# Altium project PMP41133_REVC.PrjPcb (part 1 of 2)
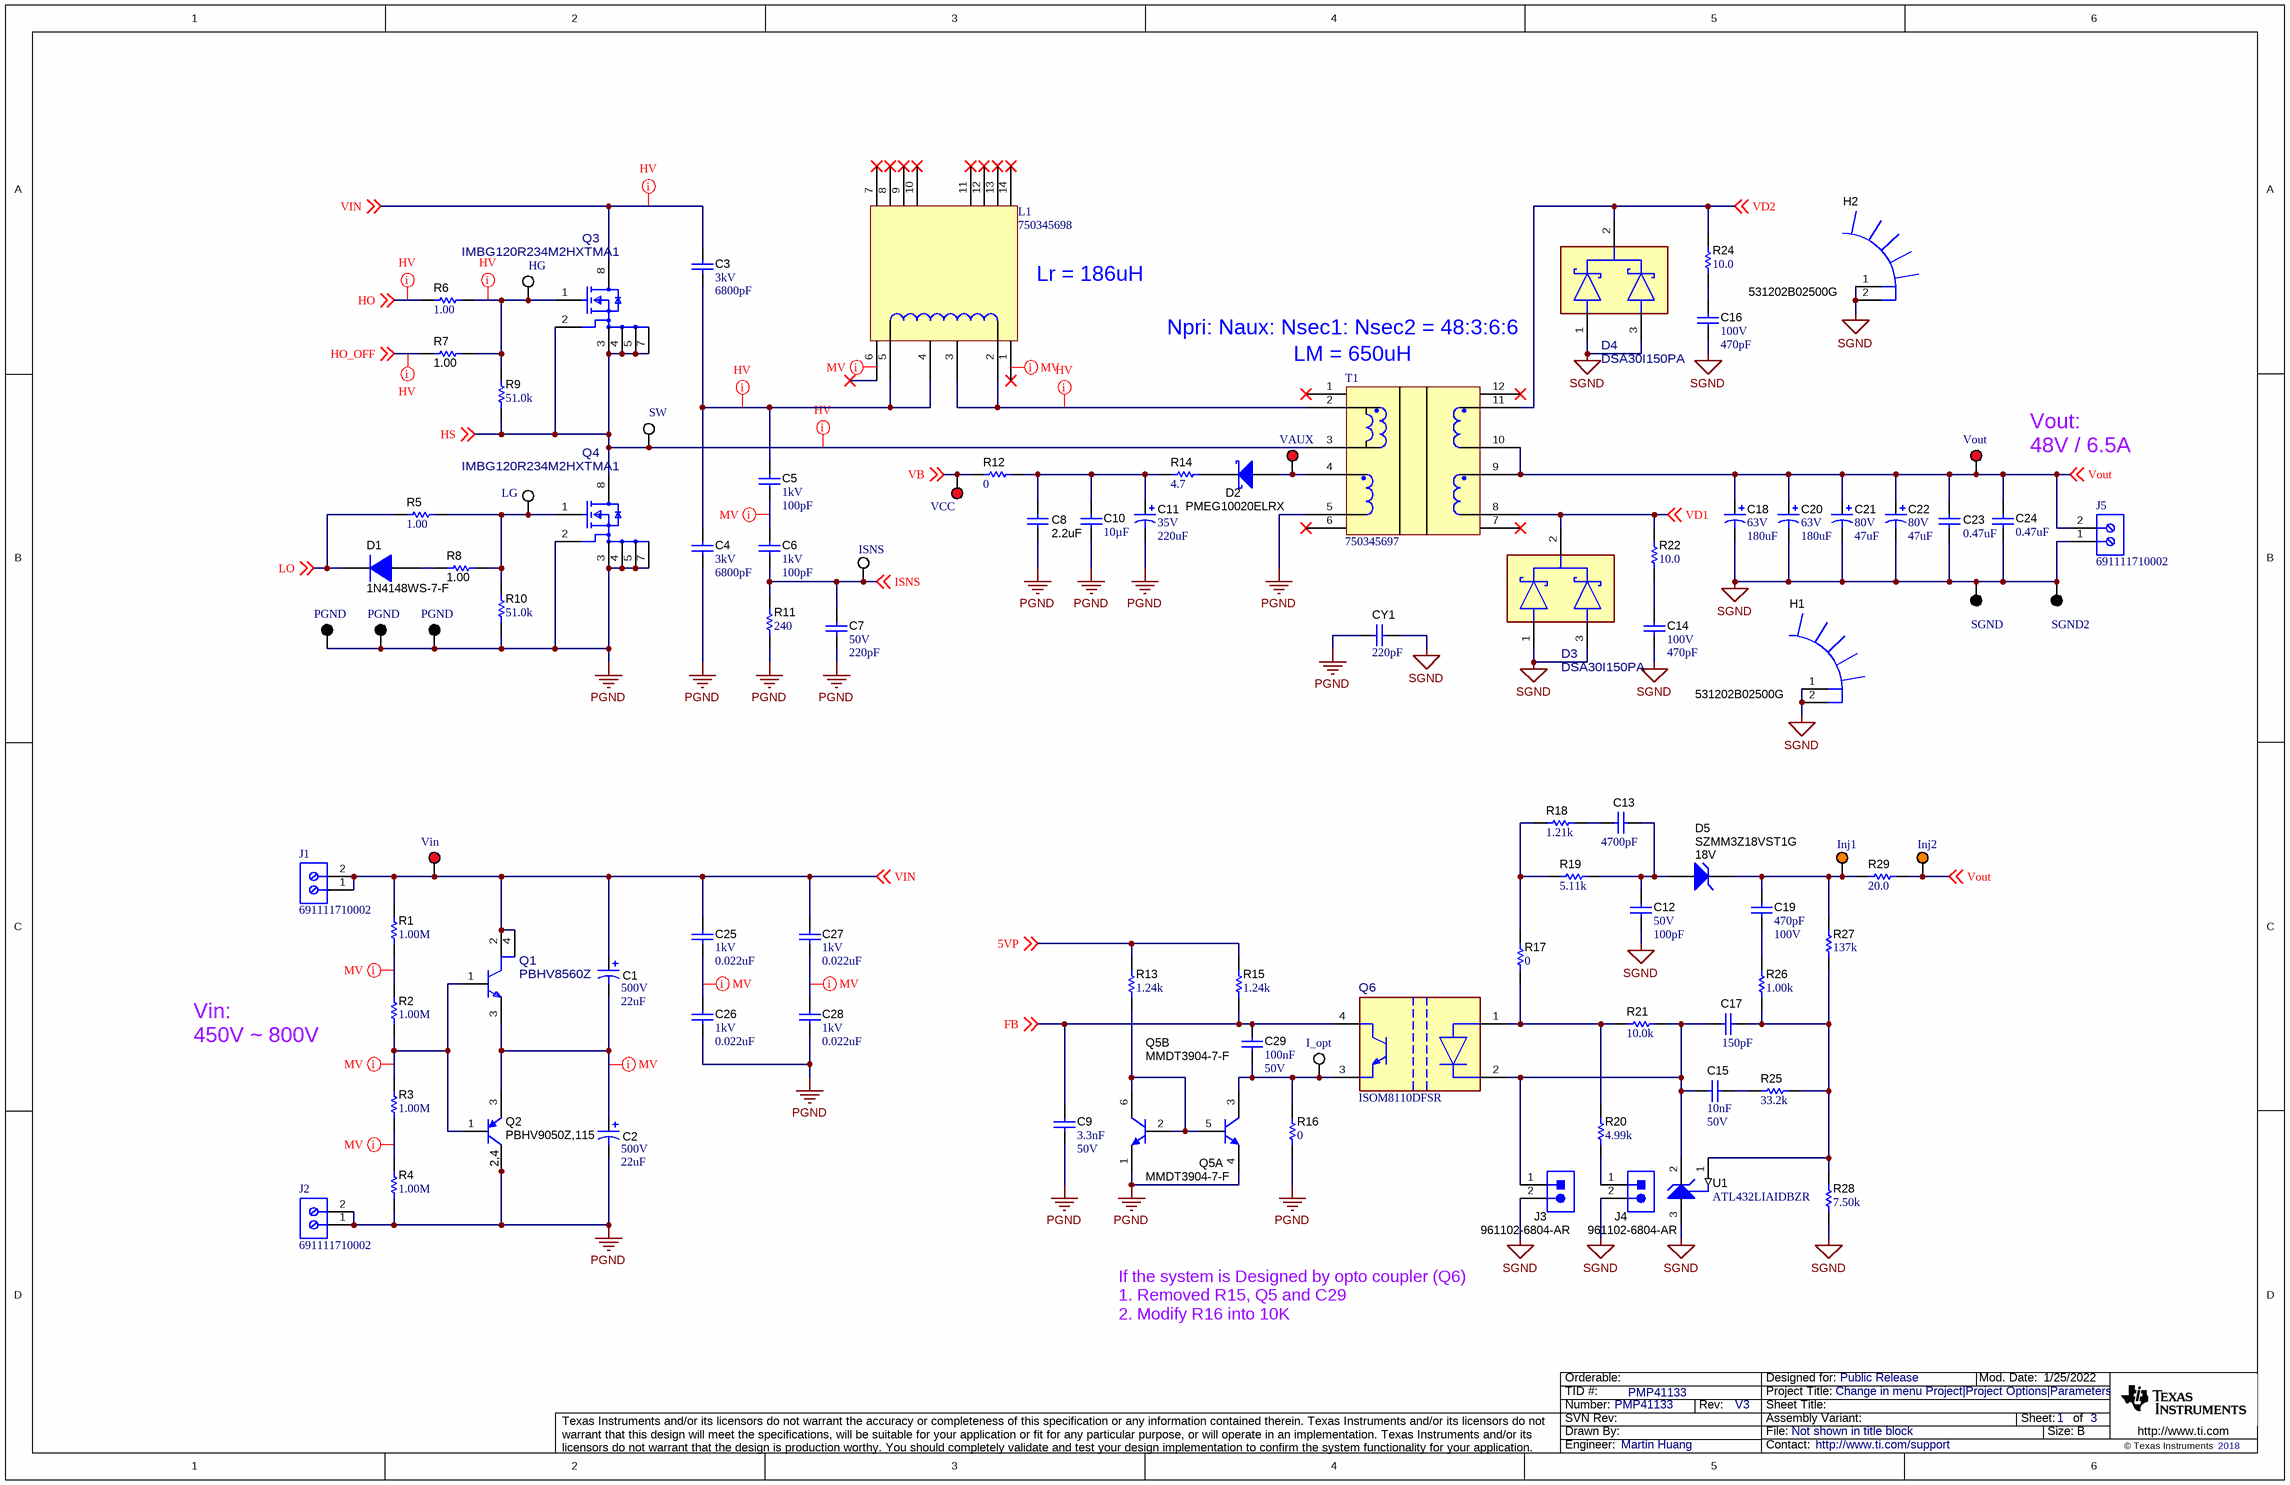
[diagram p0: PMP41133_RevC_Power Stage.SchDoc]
CopyrightYear: 2018; PCB_Layout: Martin Huang; PCB_Rev: E1; PRJ_Customer: Public Release; PRJ_Engineer: Martin Huang; PRJ_Number: PMP41133; PRJ_Title: Change in menu Project|Project Options|Parameters; SCH_Rev: V3; TechSupport: http://www.ti.com/support; TID: PMP41133
3 sheets, 184 parts. Net scope: global (net labels, ports and power ports of the same name join across sheets).
Board file: PMP41133_RevC.PcbDoc
Sheets:
  PMP41133_RevC_Power Stage.SchDoc
  PMP41133_RevC_Controller.SchDoc
  PMP41133_RevC_Hardware.SchDoc

## Sheet PMP41133_RevC_Power Stage.SchDoc
size 431 x 279 mm; Date: Not shown in title block; ApprovedBy: Not shown in title block; CheckedBy: Not shown in title block; Author: Not shown in title block; CompanyName: Not shown in title block; Engineer: Not shown in title block; Organization: Not shown in title block; Address1: Not shown in title block; Address2: Not shown in title block; Address3: Not shown in title block; Address4: Not shown in title block; DocumentNumber: 1; Revision: Use project parameter SCH_Rev; SheetNumber: 1; SheetTotal: 3; PageSetup: Record=PageOptions¦CenterHorizontal=True¦CenterVertical=True¦PrintScale=1.00¦XCorrection=1.00¦YCorrection=1.00¦PrintKind=0¦BorderSize=5000000¦LeftOffset=0¦BottomOffset=0¦Orientation=2¦PaperLength=1000¦PaperWidth=1000¦Scale=100¦PaperSource=15¦PrintQuality=600¦MediaType=1¦DitherType=10¦PaperKind=Letter¦PrintScaleMode=1

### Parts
(Parts that share a designator on the sheet are numbered #1, #2 ... from top to bottom, then left to right.)
C1  VDC_V: 500V  ValueDisplayed: 22uF  [UCY_1250x3550]  (hidden comment: UCY2H220MHD)
C2  VDC_V: 500V  ValueDisplayed: 22uF  [UCY_1250x3550]  (hidden comment: UCY2H220MHD)
C3  VDC_V: 3kV  ValueDisplayed: 6800pF  [B81123_2650x850x1650]  (hidden comment: B81123C1682M)
C4  VDC_V: 3kV  ValueDisplayed: 6800pF  [B81123_2650x850x1650]  (hidden comment: B81123C1682M)
C5  VDC_V: 1kV  ValueDisplayed: 100pF  [1206]  (hidden comment: VJ1206A101JXGAT5Z)
C6  VDC_V: 1kV  ValueDisplayed: 100pF  [1206]  (hidden comment: VJ1206A101JXGAT5Z)
C7  VDC_V: 50V  ValueDisplayed: 220pF  [0603]  (hidden comment: C0603C221K5GACTU)
C8  ValueDisplayed: 2.2uF  [0805]  (hidden comment: C2012X7R1V225K085AC)
C9  Cap_F: 3.3nF  VDC_V: 50V  [0603]  (hidden comment: GRM188R71H332KA01D)
C10  ValueDisplayed: 10µF  [1206]  (hidden comment: GRM31CR71E106MA12L)
C11  VDC_V: 35V  ValueDisplayed: 220uF  [M_800x1150]  (hidden comment: ECA-1VM221BJ)
C12  VDC_V: 50V  ValueDisplayed: 100pF  [0603]  (hidden comment: C0603C101J5GACTU)
C13  ValueDisplayed: 4700pF  [0603]  (hidden comment: GCM188R72A472KA37D)
C14  VDC_V: 100V  ValueDisplayed: 470pF  [0805]  (hidden comment: GRM2165C2A471JA01D)
C15  Cap_F: 10nF  VDC_V: 50V  [0603]  (hidden comment: GRM188R71H103KA01D)
C16  VDC_V: 100V  ValueDisplayed: 470pF  [0805]  (hidden comment: GRM2165C2A471JA01D)
C17  ValueDisplayed: 150pF  [0603]  (hidden comment: GRM1885C1H151JA01D)
C18  VDC_V: 63V  ValueDisplayed: 180uF  [UCZ_1250x1350]  (hidden comment: A783MW187M1JLASO15)
C19  Cap_F: 470pF  VDC_V: 100V  [0603]  (hidden comment: GRM188R72A471KA01D)
C20  VDC_V: 63V  ValueDisplayed: 180uF  [UCZ_1250x1350]  (hidden comment: A783MW187M1JLASO15)
C21  VDC_V: 80V  ValueDisplayed: 47uF  [PJ_800X1500]  (hidden comment: UPJ1K470MPD1TD)
C22  VDC_V: 80V  ValueDisplayed: 47uF  [PJ_800X1500]  (hidden comment: UPJ1K470MPD1TD)
C23  ValueDisplayed: 0.47uF  [0805]  (hidden comment: C2012X7S2A474K125AB)
C24  ValueDisplayed: 0.47uF  [0805]  (hidden comment: C2012X7S2A474K125AB)
C25  VDC_V: 1kV  ValueDisplayed: 0.022uF  [1206]  (hidden comment: VJ1206Y223KXGAT5Z)
C26  VDC_V: 1kV  ValueDisplayed: 0.022uF  [1206]  (hidden comment: VJ1206Y223KXGAT5Z)
C27  VDC_V: 1kV  ValueDisplayed: 0.022uF  [1206]  (hidden comment: VJ1206Y223KXGAT5Z)
C28  VDC_V: 1kV  ValueDisplayed: 0.022uF  [1206]  (hidden comment: VJ1206Y223KXGAT5Z)
C29  Cap_F: 100nF  VDC_V: 50V  [0603]  (hidden comment: C0603C104K5RACAUTO)
CY1  ValueDisplayed: 220pF  [DE1_800x700x1100]  (hidden comment: DE1B3KX221KA4BN01F)
D1  1N4148WS-7-F  [SOD-323]
D2  PMEG10020ELRX  [SOD-123W]
D3  DSA30I150PA  [FP-MBR30200CTE3_TU_TO220-3-MFG]
D4  DSA30I150PA  [FP-MBR30200CTE3_TU_TO220-3-MFG]
D5  SZMM3Z18VST1G  value 18V  [SOD-323]
H1  531202B02500G  [531202]
H2  531202B02500G  [531202]
HG  5012  [Keystone5012]  (value not drawn)
I_opt  5012  [Keystone5012]  (value not drawn)
Inj1  5013  [Keystone5013]  (value not drawn)
Inj2  5013  [Keystone5013]  (value not drawn)
ISNS  5012  [Keystone5012]  (value not drawn)
J1  691111710002  [691111710002]
J2  691111710002  [691111710002]
J3  961102-6804-AR  [3M_961102-68]
J4  961102-6804-AR  [3M_961102-68]
J5  691111710002  [691111710002]
L1  750345698  [Inductor 750345698]
LG  5012  [Keystone5012]  (value not drawn)
PGND#1  5011  [Keystone5011]  (value not drawn)
PGND#2  5011  [Keystone5011]  (value not drawn)
PGND#3  5011  [Keystone5011]  (value not drawn)
Q1  PBHV8560Z  [FP-PBHV8560Z_SOT-223-IPC_B]
Q2  PBHV9050Z,115  [SOT-223]
Q3  IMBG120R234M2HXTMA1  [FP-IMBG120R026M2HXTMA1_TO263-7-MFG]
Q4  IMBG120R234M2HXTMA1  [FP-IMBG120R026M2HXTMA1_TO263-7-MFG]
Q5  MMDT3904-7-F  [SOT-363]  (parts A,B of 2)
Q6  ISOM8110DFSR  [DFS0004A-MFG]
R1  ValueDisplayed: 1.00M  [1206]  (hidden comment: RC1206FR-071ML)
R2  ValueDisplayed: 1.00M  [1206]  (hidden comment: RC1206FR-071ML)
R3  ValueDisplayed: 1.00M  [1206]  (hidden comment: RC1206FR-071ML)
R4  ValueDisplayed: 1.00M  [1206]  (hidden comment: RC1206FR-071ML)
R5  ValueDisplayed: 1.00  [0603]  (hidden comment: RC0603FR-0742R2L)
R6  ValueDisplayed: 1.00  [0603]  (hidden comment: RC0603FR-0742R2L)
R7  ValueDisplayed: 1.00  [0603]  (hidden comment: RC0603FR-071RL)
R8  ValueDisplayed: 1.00  [0603]  (hidden comment: RC0603FR-071RL)
R9  ValueDisplayed: 51.0k  [0603]  (hidden comment: RC0603FR-0751KL)
R10  ValueDisplayed: 51.0k  [0603]  (hidden comment: RC0603FR-0751KL)
R11  ValueDisplayed: 240  [0603]  (hidden comment: RC0603FR-07240RL)
R12  ValueDisplayed: 0  [1206]  (hidden comment: CRCW12060000Z0EA)
R13  ValueDisplayed: 1.24k  [0603]  (hidden comment: RC0603FR-071K24L)
R14  ValueDisplayed: 4.7  [1206]  (hidden comment: CRCW12064R70JNEA)
R15  ValueDisplayed: 1.24k  [0603]  (hidden comment: RC0603FR-071K24L)
R16  ValueDisplayed: 0  [0603]  (hidden comment: MCR03EZPJ000)
R17  ValueDisplayed: 0  [0603]  (hidden comment: CRCW06030000Z0EA)
R18  ValueDisplayed: 1.21k  [0603]  (hidden comment: CRCW06031K21FKEA)
R19  ValueDisplayed: 5.11k  [0603]  (hidden comment: RC0603FR-075K11L)
R20  ValueDisplayed: 4.99k  [0603]  (hidden comment: CRCW06034K99FKEA)
R21  ValueDisplayed: 10.0k  [0603]  (hidden comment: RCG060310K0FKEA)
R22  ValueDisplayed: 10.0  [1206]  (hidden comment: RC1206FR-0710RL)
R24  ValueDisplayed: 10.0  [1206]  (hidden comment: RC1206FR-0710RL)
R25  ValueDisplayed: 33.2k  [0603]  (hidden comment: CRCW060333K2FKEA)
R26  ValueDisplayed: 1.00k  [0603]  (hidden comment: RC0603FR-071KL)
R27  ValueDisplayed: 137k  [0603]  (hidden comment: RC0603FR-07137KL)
R28  ValueDisplayed: 7.50k  [0603]  (hidden comment: RC0603FR-077K5L)
R29  ValueDisplayed: 20.0  [0603]  (hidden comment: CRCW06030000Z0EA)
SGND  5011  [Keystone5011]  (value not drawn)
SGND2  5011  [Keystone5011]  (value not drawn)
SW  5012  [Keystone5012]  (value not drawn)
T1  750345697  [Transformer 750345697]
U1  ATL432LIAIDBZR  [DBZ0003A_N]
VAUX  5010  [Keystone5010]  (value not drawn)
VCC  5010  [Keystone5010]  (value not drawn)
Vin  5010  [Keystone5010]  (value not drawn)
Vout  5010  [Keystone5010]  (value not drawn)

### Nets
PGND: C2.2(-) C4.2 C7.2 C8.2 C9.2 C10.2 C11.2(-) C26.2 C28.2 CY1.2 J2.1 J2.2 PGND#1.1 PGND#2.1 PGND#3.1 Q2.2(C) Q2.4(C) Q4.2(Sense) Q4.3(Source) Q4.4(Source) Q4.5(Source) Q4.7(Source) Q5.1(E) Q5.4(E) R4.1 R10.1 R11.1 R16.1 T1.5
SGND: C12.2 C14.2 C16.2 C18.2(-) C20.2(-) C21.2(-) C22.2(-) C23.1 C24.1 CY1.1 D3.1(1_ANODE) D3.3(2_ANODE) D4.1(1_ANODE) D4.3(2_ANODE) H1.1 H1.2 H2.1 H2.2 J3.2 J4.2 J5.1 R28.1 SGND.1 SGND2.1 U1.3(ANODE)
5VP: R13.2 R15.2 ; off-sheet 5VP
FB: C9.1 C29.1 Q6.4(COL) R15.1 ; off-sheet FB
HO: R6.1 ; off-sheet HO
HO_OFF: R7.1 ; off-sheet HO_OFF
HS: Q3.2(Sense) Q3.3(Source) Q3.4(Source) Q3.5(Source) Q3.7(Source) Q4.8(Drain) R9.1 SW.1 T1.3 ; off-sheet HS
ISNS: C6.2 C7.1 ISNS.1 R11.2 ; off-sheet ISNS
LO: D1.1(K) R5.1 ; off-sheet LO
VB: R12.1 VCC.1 ; off-sheet VB
VD1: D3.2(COMMON_CATHODE) R22.2 T1.8 ; off-sheet VD1
VD2: D4.2(COMMON_CATHODE) R24.2 T1.11 ; off-sheet VD2
VIN: C1.1(+) C3.1 C25.1 C27.1 J1.1 J1.2 Q1.2(C) Q1.4(C) Q3.8(Drain) R1.2 Vin.1 ; off-sheet VIN
Vout: C18.1(+) C20.1(+) C21.1(+) C22.1(+) C23.2 C24.2 Inj2.1 J5.2 R29.2 T1.9 T1.10 Vout.1 ; off-sheet Vout
NetC1_2: C1.2(-) C2.1(+) Q1.3(E) Q2.3(E)
NetC3_2: C3.2 C4.1 C5.1 L1.4 L1.5
NetC5_2: C5.2 C6.1
NetC8_1: C8.1 C10.1 C11.1(+) R12.2 R14.1
NetC12_1: C12.1 C13.1 D5.2(A) R19.2
NetC13_2: C13.2 R18.2
NetC14_1: C14.1 R22.1
NetC15_1: C15.1 C17.2 J3.1 Q6.2(CAT) R21.1 U1.2(CATHODE)
NetC15_2: C15.2 R25.2
NetC16_1: C16.1 R24.1
NetC17_1: C17.1 R25.1 R26.1 R27.1 R28.2 U1.1(REF)
NetC19_1: C19.1 D5.1(K) Inj1.1 R27.2 R29.1
NetC19_2: C19.2 R26.2
NetC25_2: C25.2 C26.1
NetC27_2: C27.2 C28.1
NetC29_2: C29.2 I_opt.1 Q5.3(C) Q6.3(EM) R16.2
NetD1_2: D1.2(A) R8.1
NetD2_1: D2.1(K) R14.2
NetD2_2: D2.2(A) T1.4 VAUX.1
NetHG_1: HG.1 Q3.1(Gate) R6.2 R7.2 R9.2
NetJ4_1: J4.1 R20.2
NetL1_2: L1.2 L1.3 T1.2
NetLG_1: LG.1 Q4.1(Gate) R5.2 R8.2 R10.2
NetQ1_1: Q1.1(B) Q2.1(B) R2.1 R3.2
NetQ5_2: Q5.2(B) Q5.5(B) Q5.6(C) R13.1
NetQ6_1: Q6.1(AN) R17.1 R20.1 R21.2
NetR1_1: R1.1 R2.2
NetR3_1: R3.1 R4.2
NetR17_2: R17.2 R18.1 R19.1

Not connected (* = marked no-connect by the designer): L1 1* 6* 7* 8* 9* 10* 11* 12* 13* 14*; T1 1* 6* 7* 12*

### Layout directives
net class HV: HO, HO_OFF, HS, NetC3_2, NetHG_1, NetL1_2, VIN
net class MV: (no net found under the mark), NetC1_2, NetC5_2, NetC25_2, NetC27_2, NetQ1_1, NetR1_1, NetR3_1

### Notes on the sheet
- (near L1) Lr = 186uH
- (near T1) LM = 650uH
- Npri: Naux: Nsec1: Nsec2 = 48:3:6:6
- Vout:
  48V / 6.5A
- Vin:
  450V ~ 800V
- If the system is Designed by opto coupler (Q6)
  1. Removed R15, Q5 and C29
  2. Modify R16 into 10K

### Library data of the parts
C1 C2 = CMP-0010255-2: CAP, AL, 22 uF, 500 V, +/- 20%, TH; Manufacturer: Nichicon; TaMin_C: -25°C; Polarized: Y; SizeAreaWB_mm2: 210.25; Value1: Unknown; Value: 22uF; TaMax_C: 105°C; SizeZ_mm: 37; SizeX_mm: 12.5; Cap_Case: 12.5x35.5mm; SizeArea_mm2: 156.25; CompType: Capacitor; AEC Qualified: N; Cap_F: 22µF; AEC Category: Q200; IRMS_A: 280mA; U/M: EA
C3 C4 = CMP-0012464-3: CAP, Film, 6800 pF, 3000 V, +/- 20%, TH; Manufacturer: TDK; TaMin_C: -40°C; Polarized: N; Value1: Unknown; Value: 6800pF; TaMax_C: 110°C; Cap_Case: 26.5x8.5x16.5mm; Value2: 3000V; Cap_F: 6.8nF; AEC Category: Q200
C5 C6 = CMP-0009030-2: CAP, CERM, 100 pF, 1000 V, +/- 5%, C0G/NP0, 1206; Manufacturer: Vishay-Vitramon; TaMin_C: -55°C; Polarized: N; SizeAreaWB_mm2: 10.92; Value1: Unknown; U/M: EA; Value: 100pF; TaMax_C: 125°C; SizeZ_mm: 1.35; SizeX_mm: 3.2; SizeY_mm: 1.6; Value2: 1000V; SizeArea_mm2: 5.12; AEC Category: Q200
C7 = CMP-0006894-1: CAP, CERM, 220 pF, 50 V, +/- 10%, C0G/NP0, 0603; Manufacturer: Kemet; TaMin_C: -55°C; Polarized: N; SizeAreaWB_mm2: 4.68; Value1: Unknown; U/M: EA; Value: 220pF; TaMax_C: 125°C; SizeZ_mm: 1; SizeX_mm: 1.6; SizeY_mm: 0.8; SizeArea_mm2: 1.28; AEC Category: Q200
C8 = CMP-0007883-2: CAP, CERM, 2.2 uF, 35 V, +/- 10%, X7R, 0805; Manufacturer: TDK; TaMin_C: -55°C; Polarized: N; SizeAreaWB_mm2: 6.75; Value1: Unknown; U/M: EA; Value: 2.2uF; TaMax_C: 125°C; SizeZ_mm: 1.45; SizeX_mm: 2; SizeY_mm: 1.25; Value2: 35V; SizeArea_mm2: 2.5; CompType: Capacitor; Cap_F: 2.2µF; AEC Category: Q200
C9 = CMP-0007450-1: CAP, CERM, 3300 pF, 50 V, +/- 10%, X7R, 0603; Manufacturer: MuRata; TaMin_C: -55°C; Polarized: N; SizeAreaWB_mm2: 4.68; Value1: Unknown; U/M: EA; Value: 3300pF; TaMax_C: 125°C; SizeZ_mm: 1; SizeX_mm: 1.6; SizeY_mm: 0.8; SizeArea_mm2: 1.28; AEC Category: Q200
C10 = CMP-0082252-1: CAP, CERM, 10 µF, 25 V,+/- 20%, X7R, AEC-Q200 Grade 1, 1206; Manufacturer: MuRata; TaMin_C: -55°C; Polarized: N; SizeAreaWB_mm2: 10.92; U/M: EA; Value: 10uF; TaMax_C: 125°C; SizeZ_mm: 1.35; SizeX_mm: 3.2; SizeY_mm: 1.6; Value2: 25V; SizeArea_mm2: 5.12; AEC Qualified: Y; AEC Grade: 1; AEC Category: Q200
C11 = CMP-0010327-2: CAP, AL, 220 uF, 35 V, +/- 20%, TH; Manufacturer: Panasonic; TaMin_C: -40°C; Polarized: Y; SizeAreaWB_mm2: 100; Value1: Unknown; U/M: EA; Value: 220uF; TaMax_C: 85°C; SizeZ_mm: 12.5; SizeX_mm: 8; Cap_Case: 8x11.5mm; SizeArea_mm2: 64; CompType: Capacitor; AEC Qualified: N; Cap_F: 220µF; IRMS_A: 350mA; AEC Category: Q200
C12 = CMP-0006841-4: CAP, CERM, 100 pF, 50 V, +/- 5%, C0G/NP0, 0603; Manufacturer: Kemet; TaMin_C: -55°C; Polarized: N; SizeAreaWB_mm2: 4.68; Value1: Unknown; U/M: EA; Value: 100pF; TaMax_C: 125°C; SizeZ_mm: 1; SizeX_mm: 1.6; SizeY_mm: 0.8; SizeArea_mm2: 1.28; AEC Category: Q200
C13 = CMP-0079247-1: CAP, CERM, 4700 pF, 100 V,+/- 10%, X7R, AEC-Q200 Grade 1, 0603; Manufacturer: MuRata; TaMin_C: -55°C; Polarized: N; SizeAreaWB_mm2: 4.68; U/M: EA; Value: 4700pF; TaMax_C: 125°C; SizeZ_mm: 1; SizeX_mm: 1.6; SizeY_mm: 0.8; Value2: 100V; SizeArea_mm2: 1.28; AEC Qualified: Y; Cap_F: 4.7nF; AEC Category: Q200
C14 C16 = CMP-0008122-2: CAP, CERM, 470 pF, 100 V, +/- 5%, C0G/NP0, 0805; Manufacturer: MuRata; TaMin_C: -55°C; Polarized: N; SizeAreaWB_mm2: 6.75; Value1: Unknown; U/M: EA; Value: 470pF; TaMax_C: 125°C; SizeZ_mm: 1.45; SizeX_mm: 2; SizeY_mm: 1.25; SizeArea_mm2: 2.5; AEC Category: Q200
C15 = CMP-0007433-1: CAP, CERM, 0.01 uF, 50 V, +/- 10%, X7R, 0603; Manufacturer: MuRata; TaMin_C: -55°C; Polarized: N; SizeAreaWB_mm2: 4.68; Value1: Unknown; U/M: EA; Value: 0.01uF; TaMax_C: 125°C; SizeZ_mm: 1; SizeX_mm: 1.6; SizeY_mm: 0.8; SizeArea_mm2: 1.28; AEC Category: Q200
C17 = CMP-0007185-4: CAP, CERM, 150 pF, 50 V, +/- 5%, C0G/NP0, 0603; Manufacturer: MuRata; TaMin_C: -55°C; Polarized: N; SizeAreaWB_mm2: 4.68; Value1: Unknown; U/M: EA; Value: 150pF; TaMax_C: 125°C; SizeZ_mm: 1; SizeX_mm: 1.6; SizeY_mm: 0.8; Value2: 50V; SizeArea_mm2: 1.28; AEC Category: Q200
C18 C20 = CMP-0011410-2: CAP, AL HYBRID, 180 uF, 63 V, +/- 20%, 0.015 ohm, SMD; Manufacturer: Nichicon; PartNumber: UCZ1J181MNQ1MS; TaMin_C: -40°C; ESR_ohm: 0.2; Polarized: Y; SizeAreaWB_mm2: 258.96; Value1: 0.2 ohm; U/M: EA; Value: 180uF; TaMax_C: 125°C; SizeZ_mm: 14.5; SizeX_mm: 14.6; SizeY_mm: 13.6; Cap_Case: 12.5x13.5mm; SizeArea_mm2: 198.56; CompType: Capacitor; Cap_F: 180µF; IRMS_A: 1A; AEC Grade: 1; AEC Category: Q200
C19 = CMP-0007482-4: CAP, CERM, 470 pF, 100 V, +/- 10%, X7R, 0603; Manufacturer: MuRata; TaMin_C: -55°C; Polarized: N; SizeAreaWB_mm2: 4.68; Value1: Unknown; U/M: EA; Value: 470pF; TaMax_C: 125°C; SizeZ_mm: 1; SizeX_mm: 1.6; SizeY_mm: 0.8; SizeArea_mm2: 1.28; AEC Category: Q200
C21 C22 = CMP-0009929-2: CAP, AL, 47 uF, 80 V, +/- 20%, TH; Manufacturer: Nichicon; TaMin_C: -55°C; Polarized: Y; SizeAreaWB_mm2: 100; Value1: Unknown; U/M: EA; Value: 47uF; TaMax_C: 105°C; SizeZ_mm: 16; SizeX_mm: 8; Cap_Case: 8x15mm; SizeArea_mm2: 64; CompType: Capacitor; Cap_F: 47µF; AEC Category: Q200
C23 C24 = CMP-0007895-2: CAP, CERM, 0.47 uF, 100 V, +/- 10%, X7S, 0805; Manufacturer: TDK; TaMin_C: -55°C; Polarized: N; SizeAreaWB_mm2: 6.75; Value1: 0.017152 ohm; U/M: EA; Value: 0.47uF; TaMax_C: 125°C; SizeZ_mm: 1.45; SizeX_mm: 2; SizeY_mm: 1.25; Value2: 100V; SizeArea_mm2: 2.5; Cap_F: 470nF; AEC Category: Q200; ESR_ohm: 17.152m; IRMS_A: 1.5807A
C25-C28 = CMP-0009052-2: CAP, CERM, 0.022 uF, 1000 V, +/- 10%, X7R, 1206; Manufacturer: Vishay-Vitramon; TaMin_C: -55°C; Polarized: N; SizeAreaWB_mm2: 10.92; Value1: Unknown; U/M: EA; TaMax_C: 125°C; SizeZ_mm: 1.35; SizeX_mm: 3.2; SizeY_mm: 1.6; Value2: 1000V; SizeArea_mm2: 5.12; Cap_F: 22nF; AEC Category: Q200
C29 = CMP-0079602-1: CAP, CERM, 0.1 µF, 50 V,+/- 10%, X7R, AEC-Q200 Grade 1, 0603; Manufacturer: Kemet; TaMin_C: -55°C; Polarized: N; SizeAreaWB_mm2: 4.68; U/M: EA; Value: 0.1uF; TaMax_C: 125°C; SizeZ_mm: 1; SizeX_mm: 1.6; SizeY_mm: 0.8; SizeArea_mm2: 1.28; AEC Qualified: Y; AEC Category: Q200; ValueDisplayed: 0.1µF
CY1 = CMP-0077649-1: CAP, CERM, 220 pF,  V,+/- 10%, B, D8xT7mm; Manufacturer: MuRata; SizeAreaWB_mm2: 113.4; VAC_X: 250; VAC_Y: 300; SizeArea_mm2: 74.2; AEC Qualified: N; AEC Category: Q200; Value: 220pF; TaMax_C: 125°C; SizeZ_mm: 11.0; TaMin_C: -40°C; SizeY_mm: 7.0; U/M: EA; AC_Safety: X1, Y1; SizeX_mm: 10.6; Cap_Case: 8x7x11mm
D1 = CMP-0079597-1: Diode, Switching, 75 V, 0.15 A, AEC-Q101, SOD-323; Manufacturer: Diodes Inc.; SizeAreaWB_mm2: 8.695; Vr_V: 75V; SizeArea_mm2: 3.645; AEC Qualified: Y; TJmax_C: 150°C; AEC Category: Q101; Value: 75V; SizeZ_mm: 1; Io_A: 150mA; Vf_V: 1.25V; SizeY_mm: 1.35; Value1: 0.15A; SizeX_mm: 2.7
D2 = CMP-0028977-2: Diode, Schottky, 100 V, 2 A, AEC-Q101, SOD-123W; Manufacturer: Nexperia; Io_A: 2A; SizeAreaWB_mm2: 12.15; Vr_V: 100V; TJmax_C: 175°C; Value: 100V; SizeZ_mm: 1; SizeX_mm: 3.5; SizeY_mm: 1.7; Vf_V: 830mV; Value2: 0.83V; SizeArea_mm2: 5.95; AEC Qualified: Y; AEC Category: Q101
D3 D4 = CMP-0089434-2: Common Cathode Schottky 150V 30A Through Hole TO-220-3; Manufacturer: Microsemi; PartNumber: MBR30200CTE3/TU; TJmax_C: 175°C; SizeZ_mm: 0.801inch; Vf_V: 200V; CompType: Diode; AEC Qualified: No; AEC Category: Q101; Max Surge Forward Current: 275A; Peak Reverse Current: 0.05mA
D5 = CMP-0085765-1: Diode, Zener, 18 V, 300 mW, AEC-Q101, SOD-323; Manufacturer: ON Semiconductor; Value1: 0.3W; SizeX_mm: 2.7; RJA_CperW: 416; SizeArea_mm2: 3.645; AEC Category: Q101; SizeZ_mm: 1; Power_W: 300mW; AEC Qualified: Y; SizeY_mm: 1.35; SizeAreaWB_mm2: 8.695
H1 H2 = CMP-0004053-1: Manufacturer: Aavid; Note: footprint renamed from HSINK_531202B025B025 to 531202; CompType: Heat Sink
HG I_opt ISNS LG SW = CMP-0055149-2: Test Point, Multipurpose, White, TH; Manufacturer: Keystone Electronics; CNHeader: FALSE; Green_Lifecycle: Active; Green_REACh: Passed; ContactFinish: Silver; CT: TRUE
Inj1 Inj2 = CMP-0055150-2: Test Point, Multipurpose, Orange, TH; Manufacturer: Keystone Electronics; CNHeader: FALSE; Green_Lifecycle: Active; Green_REACh: Passed; ContactFinish: Silver; CT: TRUE
J1 J2 J5 = CMP-1502-03262-2: NexarPartId: 8917708; Manufacurer: Würth Elektronik; Voltage Rating: 300V; Stripping Length: -6mm; Number of Positions Per Level: 2; Pitch: 5.0038mm; Wire/Cable Gauge: 26AWG; Current Rating: 8A; Number of Levels: 1
J3 J4 = CMP-0075355-1: Header, 2.54mm, 2x1, Gold, TH; Manufacturer: 3M; CNHeader: True; Current_A: 2A; Shrouded: N; Gender: Male; Row_Count: 1; Pitch_mm: 2.54; CT: False; Cert_UL: Y
L1 = Inductor 750345698: Customized resonant inductor; L = 186uH; Manufacturer: Wurth
PGND#1-PGND#3 SGND SGND2 = CMP-0055148-2: Test Point, Multipurpose, Black, TH; Manufacturer: Keystone Electronics; CNHeader: FALSE; Green_Lifecycle: Active; Green_REACh: Passed; ContactFinish: Silver; CT: TRUE
Q1 = CMP-0089779-1: Bipolar (BJT) Transistor NPN 600V 500mA  650mW Surface Mount SOT-223; Manufacturer: Nexperia; AEC Grade: Grade 0; Hfe Testvce: 10V; Hfe Max: 135; Vcesat1_V: 50mV; Number Of Elements: 1; AEC Qualified: Yes; SizeZ_mm: 1.8mm; TaMin_C: -55°C; TaMax_C: 150°C; Standoff Height: 0.01mm; TJmax_C: +150°C; Hfe Min: 70; Rthja Max: 190K/W; Emitter Base Voltage: 6V; Hfe Testic: 50mA; Power_W: 0.65W
Q2 = CMP-0000371-2: Transistor, PNP, 500 V, 0.25 A, AEC-Q101, SOT-223; Manufacturer: NXP Semiconductor; TaMax_C: 150°C; Value2: 300; Value1: 0.25 A; Vcesat1_V: 95mV; SizeX_mm: 6.5; SizeY_mm: 7; TaMin_C: -55°C; IcRated_A: 250mA; CompType: BJT; SizeZ_mm: 1.6; AEC Qualified: Y; Value: 500 V; SizeArea_mm2: 45.5; NPN: 0; Vceo_V: 500V; PNP: 1; AEC Category: Q101; SizeAreaWB_mm2: 76.5; U/M: EA
Q3 Q4 = CMP-0124581-1: N-Channel 1200 V 8.1A (Tc) 80W (Tc) Surface Mount PG-TO263-7-12; Manufacturer: Infineon; AEC Qualified: No; IdsMax_A: 75A; QgTyp_nC: 60nC @ 18V; Rdson45_ohm: 25.4m; SizeZ_mm: 4.5mm; VdsMax_V: 5.5V; Vgs_V: 23V; Input Capacitance At Vds: 1990pF @ 800V; Number Of Channels: 1; Power_W: 335W; Pulse Drain Current: 159A; Reverse Recovery Charge: 290nC; Rthja Max: 62K/W; Standoff Height: 0.1mm; Threshold Vgs Max: 5.1V; Threshold Vgs Min: 3.5V; TJmax_C: +175°C; Transconductance: 18.3S; Turn Off Delay Time: 9.7ns; Turn On Delay Time: 5ns; Typ Forward Diode Voltage: 4.2V
Q5 = CMP-0000396-2: Transistor, Dual NPN, 40 V, 0.2 A, SOT-363; Manufacturer: Diodes Inc.; TaMax_C: 150°C; Value2: 300; Value1: 0.2 A; Vcesat1_V: 300mV; SizeX_mm: 2.2; TaMin_C: -55°C; IcRated_A: 200mA; CompType: BJT; SizeZ_mm: 1.1; Value: 40 V; SizeArea_mm2: 4.84; NPN: 2; Vceo_V: 40V; PNP: 0; AEC Category: Q101; SizeAreaWB_mm2: 10.24; U/M: EA
Q6 = CMP-0121852-1: 3.75-kVRMS, Single-Channel Opto-Emulator with Analog Transistor Output; Manufacturer: Texas Instruments; SizeZ_mm: 2.6mm; AEC Qualified: No; CTR (Max): 195%; CTR (Min): 55%; Emiiter Collector Voltage: 7V; Forward Current: 5mA; Power_TotalModule: 290mW; Standoff Height: 0.05mm; TaMax_C: +125°C; TaMin_C: -55°C; TJmax_C: +150°C; Value: 80V; Vf_V: 1.2V; Voltage_Isolation_Vrms: 3750Vrms
R1-R4 = CMP-0018027-2: RES, 1.00 M, 1%, 0.25 W, 1206; Manufacturer: Yageo America; Power_W: 250mW; TempCo: 100 ppm/C; Value_Code: 1M00; U/M: EA; Value: 1.00Meg; EIA_Code: E96; Res_ohm: 1M; SizeX_mm: 3.2; SizeY_mm: 1.6; SizeZ_mm: 1.35; Value2: 0.25W; SizeArea_mm2: 5.12; VDC_V: 200V; AEC Category: Q200
R5 R6 = CMP-0022170-4: RES, 1.00, 1%, 0.1 W, AEC-Q200 Grade 0, 0603; Manufacturer: Vishay-Dale; PartNumber: CRCW06031R00FKEA; Power_W: 100mW; TempCo: 100 ppm/C; Value_Code: 1R00; Value: 1.00; EIA_Code: E96; Res_ohm: 1; SizeX_mm: 1.6; SizeY_mm: 0.8; Value2: 0.1W; SizeArea_mm2: 1.28; AEC Qualified: Y; VDC_V: 75V; AEC Category: Q200; AEC Grade: 0
R7 R8 = CMP-0022900-4: RES, 1.00, 1%, 0.1 W, 0603; Manufacturer: Yageo; Power_W: 100mW; TempCo: 200 ppm/C; Value_Code: 1R00; Value: 1.00; EIA_Code: E96; Res_ohm: 1; SizeX_mm: 1.6; SizeY_mm: 0.8; Value2: 0.1W; SizeArea_mm2: 1.28; CompType: Resistor; AEC Qualified: N; VDC_V: 75V; AEC Category: Q200; SizeAreaWB_mm2: 4.68
R9 R10 = CMP-0023167-5: RES, 51.0 k, 1%, 0.1 W, 0603; Manufacturer: Yageo; Power_W: 100mW; TempCo: 100 ppm/C; Value_Code: 51k0; Value: 51.0k; Res_ohm: 51k; SizeX_mm: 1.6; SizeY_mm: 0.8; SizeZ_mm: 1; Value2: 0.1W; SizeArea_mm2: 1.28; AEC Qualified: N; VDC_V: 75V; AEC Category: Q200; SizeAreaWB_mm2: 4.68
R11 = CMP-0022938-5: RES, 240, 1%, 0.1 W, 0603; Manufacturer: Yageo; Power_W: 100mW; TempCo: 100 ppm/C; Value_Code: 240R; Value: 240; SizeX_mm: 1.6; SizeY_mm: 0.8; SizeZ_mm: 1; Value2: 0.1W; SizeArea_mm2: 1.28; AEC Qualified: N; VDC_V: 75V; AEC Category: Q200; SizeAreaWB_mm2: 4.68
R12 = CMP-0018573-3: RES, 0, 5%, 0.25 W, AEC-Q200 Grade 0, 1206; Manufacturer: Vishay-Dale; Power_W: 250mW; TempCo: 200 ppm/C; Value_Code: 0000; Value: 0; EIA_Code: E24; SizeX_mm: 3.2; SizeY_mm: 1.6; SizeZ_mm: 1.35; Value2: 0.25W; SizeArea_mm2: 5.12; AEC Qualified: Y; VDC_V: 200V; AEC Category: Q200
R13 R15 = CMP-0022872-5: RES, 1.24 k, 1%, 0.1 W, 0603; Manufacturer: Yageo; Power_W: 100mW; TempCo: 100 ppm/C; Value_Code: 1k24; Value: 1.24k; EIA_Code: E96; SizeX_mm: 1.6; SizeY_mm: 0.8; SizeZ_mm: 1; Value2: 0.1W; SizeArea_mm2: 1.28; AEC Qualified: N; VDC_V: 75V; AEC Category: Q200; SizeAreaWB_mm2: 4.68
R14 = CMP-0018693-3: RES, 4.7, 5%, 0.25 W, AEC-Q200 Grade 0, 1206; Manufacturer: Vishay-Dale; Power_W: 250mW; TempCo: 200 ppm/C; Value_Code: 4R70; Value: 4.7; EIA_Code: E24; SizeX_mm: 3.2; SizeY_mm: 1.6; SizeZ_mm: 1.35; Value2: 0.25W; SizeArea_mm2: 5.12; AEC Qualified: Y; VDC_V: 200V; AEC Category: Q200; AEC Grade: 0
R16 = CMP-0025883-1: RES, 0, 5%, 0.1 W, 0603; Manufacturer: Rohm; Power_W: 100mW; TempCo: 400 ppm/C; Value_Code: 0000; U/M: EA; Value: 0; EIA_Code: E24; SizeX_mm: 1.6; SizeY_mm: 0.8; SizeZ_mm: 1; Value2: 0.1W; SizeArea_mm2: 1.28; AEC Qualified: N; VDC_V: 50V; AEC Category: Q200
R17 = CMP-0025697-4: RES, 0, 5%, 0.1 W, AEC-Q200 Grade 0, 0603; Manufacturer: Vishay-Dale; Value: 0; SizeY_mm: 0.8; SizeX_mm: 1.6; TempCo: 200 ppm/C; SizeArea_mm2: 1.28; Value_Code: 0000; EIA_Code: E24; Power_W: 100mW; AEC Qualified: Y; SizeZ_mm: 1; Value2: 0.1W; AEC Category: Q200; VDC_V: 75V
R18 = CMP-0022117-4: RES, 1.21 k, 1%, 0.1 W, AEC-Q200 Grade 0, 0603; Manufacturer: Vishay-Dale; Power_W: 100mW; TempCo: 100 ppm/C; Value_Code: 1k21; Value: 1.21k; EIA_Code: E96; SizeX_mm: 1.6; SizeY_mm: 0.8; SizeZ_mm: 1; Value2: 0.1W; SizeArea_mm2: 1.28; AEC Qualified: Y; VDC_V: 75V; AEC Category: Q200; AEC Grade: 0
R19 = CMP-0023197-5: RES, 5.11 k, 1%, 0.1 W, 0603; Manufacturer: Yageo; Power_W: 100mW; TempCo: 100 ppm/C; Value_Code: 5k11; Value: 5.11k; EIA_Code: E96; SizeX_mm: 1.6; SizeY_mm: 0.8; SizeZ_mm: 1; Value2: 0.1W; SizeArea_mm2: 1.28; AEC Qualified: N; VDC_V: 75V; AEC Category: Q200; SizeAreaWB_mm2: 4.68
R20 = CMP-0022458-4: RES, 4.99 k, 1%, 0.1 W, AEC-Q200 Grade 0, 0603; Manufacturer: Vishay-Dale; Value: 4.99k; SizeY_mm: 0.8; SizeX_mm: 1.6; TempCo: 100 ppm/C; SizeArea_mm2: 1.28; Value_Code: 4k99; EIA_Code: E96; Power_W: 100mW; AEC Qualified: Y; SizeZ_mm: 1; AEC Grade: 0; Value2: 0.1W; AEC Category: Q200; VDC_V: 75V
R21 = CMP-0023337-1: RES, 10.0 k, 1%, 0.1 W, 0603; Manufacturer: Vishay Draloric; Power_W: 100mW; TempCo: 100 ppm/C; Value_Code: 10k0; U/M: EA; Value: 10.0k; EIA_Code: E96; Res_ohm: 10k; SizeX_mm: 1.6; SizeY_mm: 0.8; SizeZ_mm: 1; Value2: 0.1W; SizeArea_mm2: 1.28; AEC Qualified: N; VDC_V: 75V; AEC Category: Q200
R22 R24 = CMP-0017851-2: RES, 10.0, 1%, 0.25 W, 1206; Manufacturer: Yageo America; Power_W: 250mW; TempCo: 200 ppm/C; Value_Code: 10R0; U/M: EA; Value: 10.0; EIA_Code: E96; Res_ohm: 10; SizeX_mm: 3.2; SizeY_mm: 1.6; SizeZ_mm: 1.35; Value2: 0.25W; SizeArea_mm2: 5.12; VDC_V: 200V; AEC Category: Q200
R25 = CMP-0022339-4: RES, 33.2 k, 1%, 0.1 W, AEC-Q200 Grade 0, 0603; Manufacturer: Vishay-Dale; Power_W: 100mW; TempCo: 100 ppm/C; Value_Code: 33k2; Value: 33.2k; EIA_Code: E96; SizeX_mm: 1.6; SizeY_mm: 0.8; SizeZ_mm: 1; Value2: 0.1W; SizeArea_mm2: 1.28; AEC Qualified: Y; VDC_V: 75V; AEC Category: Q200; AEC Grade: 0
R26 = CMP-0022895-5: RES, 1.00 k, 1%, 0.1 W, 0603; Manufacturer: Yageo; Power_W: 100mW; TempCo: 100 ppm/C; Value_Code: 1k00; Value: 1.00k; EIA_Code: E96; Res_ohm: 1k; SizeX_mm: 1.6; SizeY_mm: 0.8; SizeZ_mm: 1; Value2: 0.1W; SizeArea_mm2: 1.28; AEC Qualified: N; VDC_V: 75V; AEC Category: Q200; SizeAreaWB_mm2: 4.68
R27 = CMP-0022788-4: RES, 137 k, 1%, 0.1 W, 0603; Manufacturer: Yageo; Power_W: 100mW; TempCo: 100 ppm/C; Value: 137k; EIA_Code: E96; SizeX_mm: 1.6; SizeY_mm: 0.8; SizeZ_mm: 1; Value2: 0.1W; SizeArea_mm2: 1.28; AEC Qualified: N; VDC_V: 75V; AEC Category: Q200; SizeAreaWB_mm2: 4.68
R28 = CMP-0023279-5: RES, 7.50 k, 1%, 0.1 W, 0603; Manufacturer: Yageo; Power_W: 100mW; TempCo: 100 ppm/C; Value_Code: 7k50; Value: 7.50k; EIA_Code: E96; Res_ohm: 7.5k; SizeX_mm: 1.6; SizeY_mm: 0.8; SizeZ_mm: 1; Value2: 0.1W; SizeArea_mm2: 1.28; AEC Qualified: N; VDC_V: 75V; AEC Category: Q200; SizeAreaWB_mm2: 4.68
R29 = CMP-0022206-3: RES, 20.0, 1%, 0.1 W, 0603; Manufacturer: Vishay-Dale; PartNumber: CRCW060320R0FKEA; Power_W: 100mW; TempCo: 100 ppm/C; Value_Code: 20R0; U/M: EA; Value: 20.0; EIA_Code: E96; Res_ohm: 20; SizeX_mm: 1.6; SizeY_mm: 0.8; SizeZ_mm: 1; Value2: 0.1W; SizeArea_mm2: 1.28; VDC_V: 75V; AEC Category: Q200
T1 = Component_1: Customized LLC transformer. Lp = 650uH; Manufacturer: Wurth
U1 = CMP-0860484-1: High-bandwidth low-IQ programmable shunt regulator, DBZ0003A (SOT-23-3); Alternate Manufacturer: Texas Instruments; SizeArea_mm2: 7.5; SizeAreaWB_mm2: 14; Rating: Catalog; SizeX_mm: 2.5; SizeY_mm: 3; CompType: IC; SizeZ_mm: 1.12; AEC Category: Q200; AEC Qualified: N
VAUX VCC Vin Vout = CMP-0055147-2: Test Point, Multipurpose, Red, TH; Manufacturer: Keystone Electronics; CNHeader: FALSE; Green_Lifecycle: Active; Green_REACh: Passed; ContactFinish: Silver; CT: TRUE

## Sheet PMP41133_RevC_Controller.SchDoc
size 431 x 279 mm; Date: Not shown in title block; ApprovedBy: Not shown in title block; CheckedBy: Not shown in title block; Author: Not shown in title block; CompanyName: Not shown in title block; Engineer: Not shown in title block; Organization: Not shown in title block; Address1: Not shown in title block; Address2: Not shown in title block; Address3: Not shown in title block; Address4: Not shown in title block; DocumentNumber: 2; Revision: Use project parameter SCH_Rev; SheetNumber: 2; SheetTotal: 3; PageSetup: Record=PageOptions¦CenterHorizontal=True¦CenterVertical=True¦PrintScale=1.00¦XCorrection=1.00¦YCorrection=1.00¦PrintKind=0¦BorderSize=5000000¦LeftOffset=0¦BottomOffset=0¦Orientation=2¦PaperLength=1000¦PaperWidth=1000¦Scale=100¦PaperSource=15¦PrintQuality=600¦MediaType=1¦DitherType=10¦PaperKind=Letter¦PrintScaleMode=1
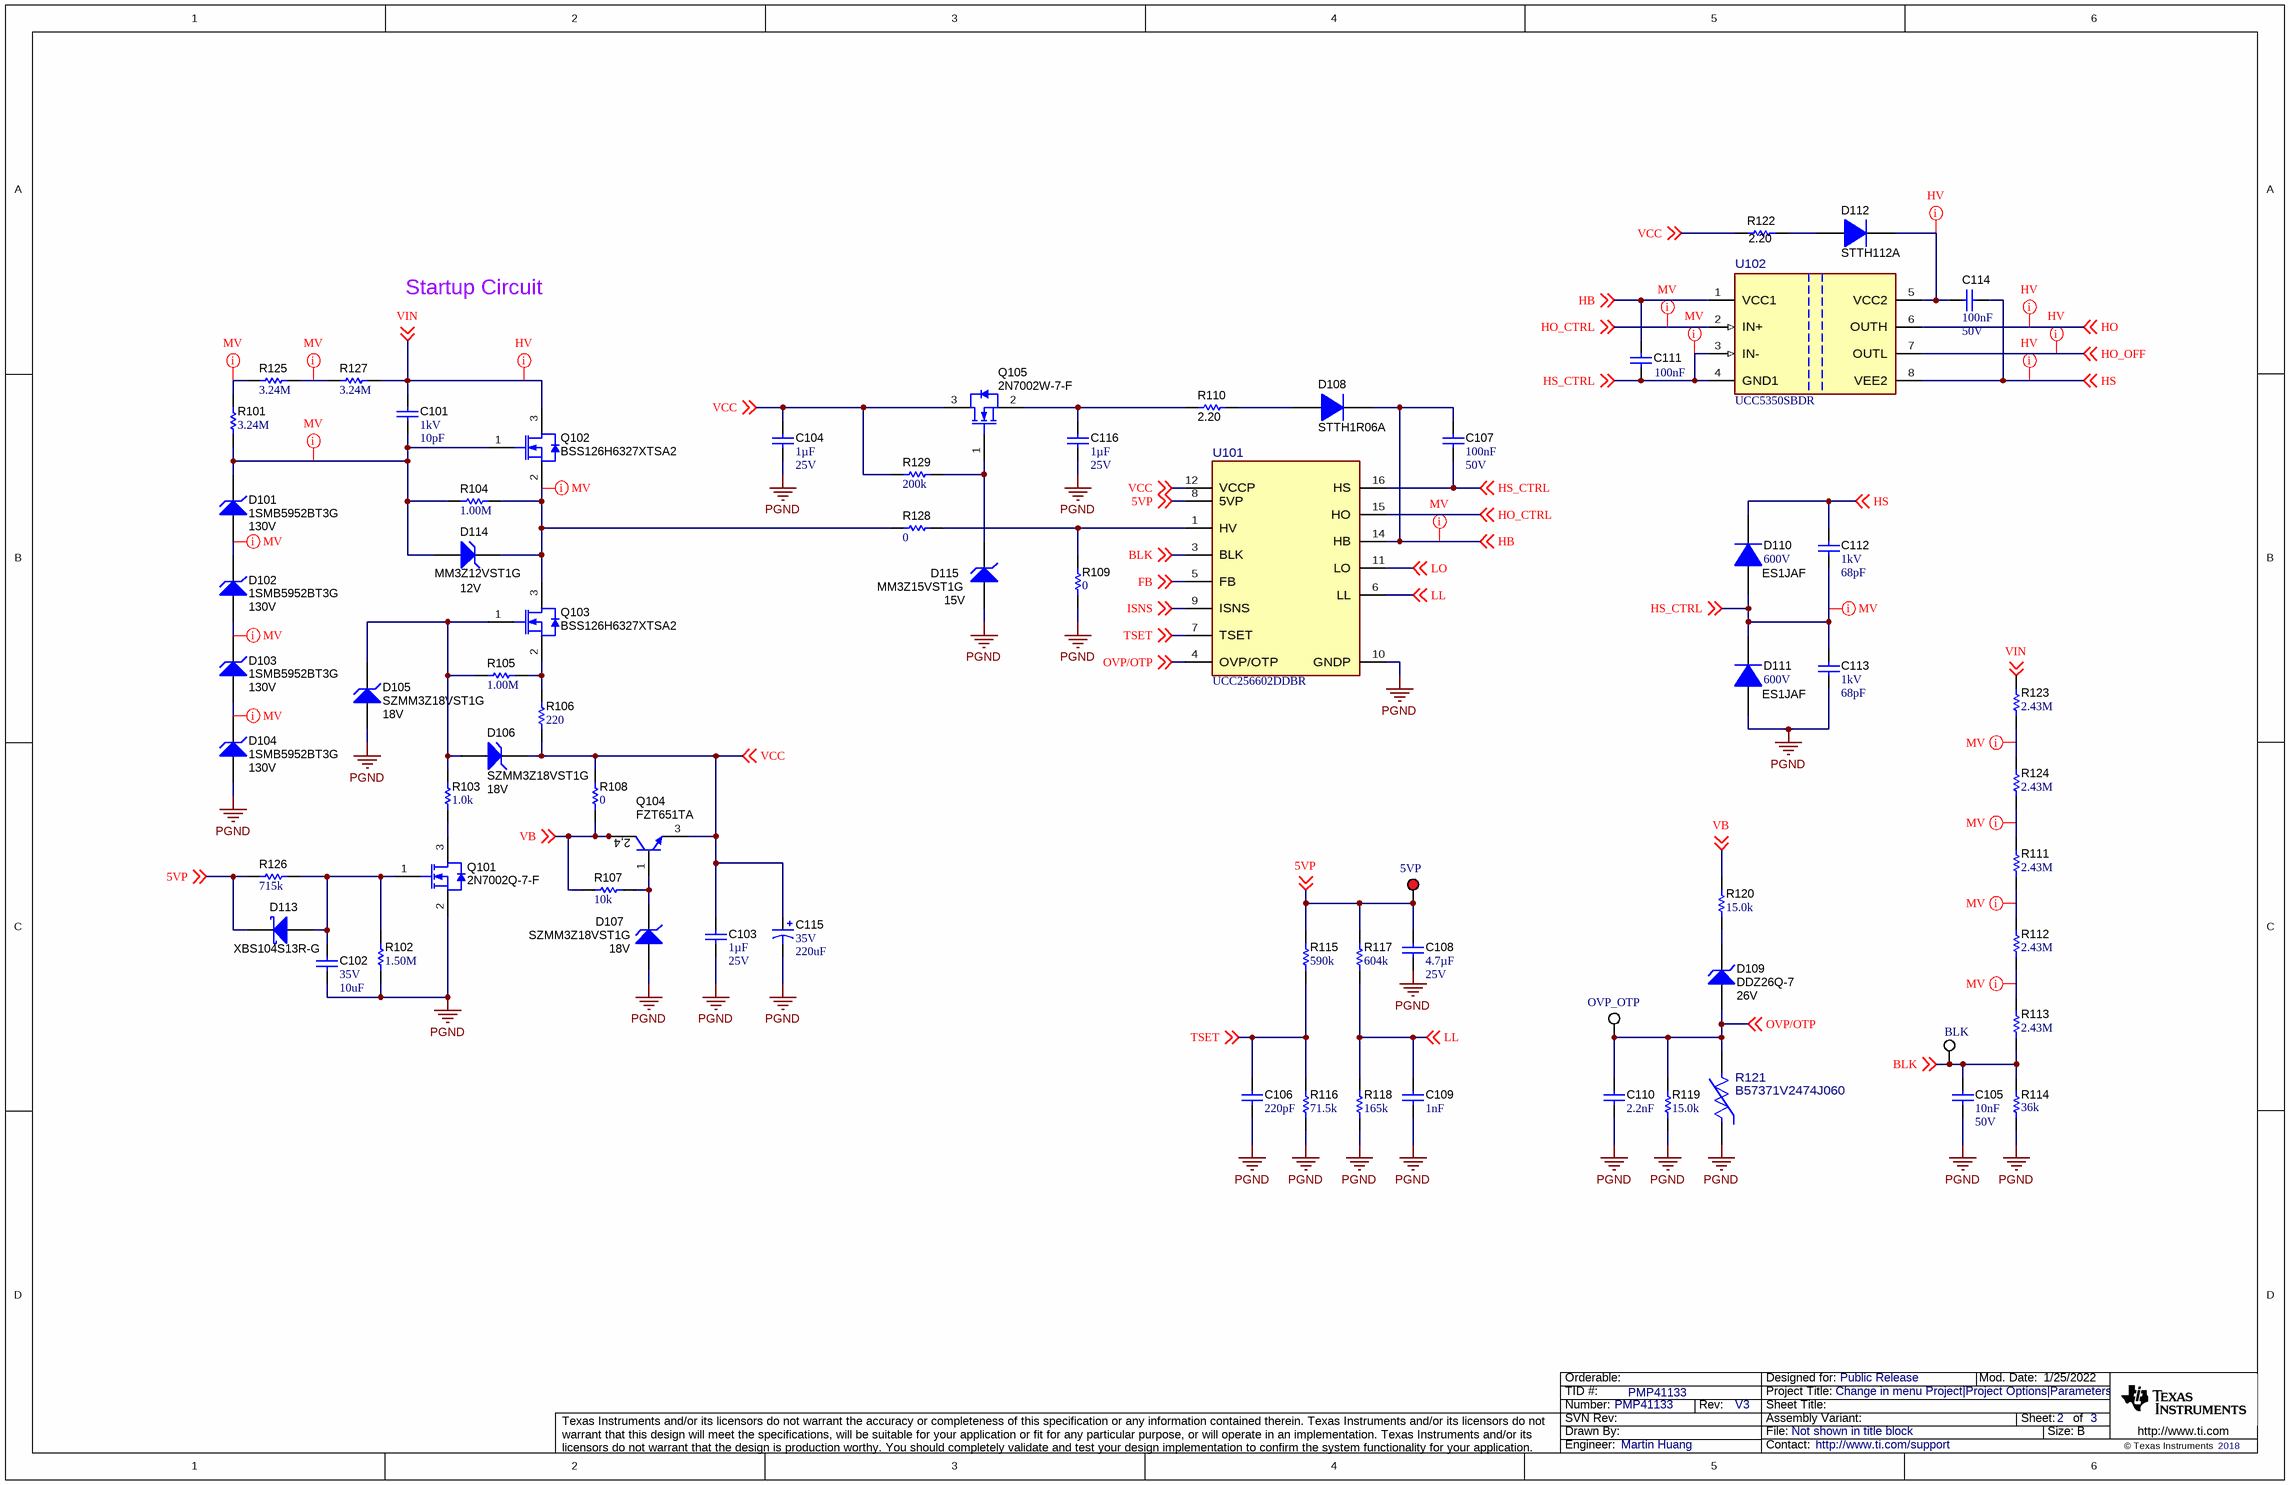
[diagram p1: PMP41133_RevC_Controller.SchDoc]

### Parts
5VP  5010  [Keystone5010]  (value not drawn)
BLK  5012  [Keystone5012]  (value not drawn)
C101  VDC_V: 1kV  ValueDisplayed: 10pF  [1206]  (hidden comment: VJ1206A100JXGAT5Z)
C102  VDC_V: 35V  ValueDisplayed: 10uF  [0603]  (hidden comment: GRM188R6YA106MA73)
C103  Cap_F: 1µF  VDC_V: 25V  [0603]  (hidden comment: CGA3E1X7R1E105K080AC)
C104  Cap_F: 1µF  VDC_V: 25V  [0603]  (hidden comment: CGA3E1X7R1E105K080AC)
C105  Cap_F: 10nF  VDC_V: 50V  [0603]  (hidden comment: GRM188R71H103KA01D)
C106  Cap_F: 220pF  [0603]  (hidden comment: C0603X221K5RACTU)
C107  Cap_F: 100nF  VDC_V: 50V  [0603]  (hidden comment: C0603C104K5RACTU)
C108  Cap_F: 4.7µF  VDC_V: 25V  [0805_HV]  (hidden comment: GRM21BR71E475KA73L)
C109  Cap_F: 1nF  [0603]  (hidden comment: C0603X102K5RACTU)
C110  Cap_F: 2.2nF  [0603]  (hidden comment: C0603X222K5RACTU)
C111  Cap_F: 100nF  [0603]  (hidden comment: GCM188R71E104KA57D)
C112  VDC_V: 1kV  ValueDisplayed: 68pF  [1206]  (hidden comment: GRM31A7U3A680JW31D)
C113  VDC_V: 1kV  ValueDisplayed: 68pF  [1206]  (hidden comment: GRM31A7U3A680JW31D)
C114  Cap_F: 100nF  VDC_V: 50V  [0603]  (hidden comment: C0603C104K5RACTU)
C115  VDC_V: 35V  ValueDisplayed: 220uF  [M_800x1150]  (hidden comment: ECA-1VM221BJ)
C116  Cap_F: 1µF  VDC_V: 25V  [0603]  (hidden comment: CGA3E1X7R1E105K080AC)
D101  1SMB5952BT3G  value 130V  [SMB]
D102  1SMB5952BT3G  value 130V  [SMB]
D103  1SMB5952BT3G  value 130V  [SMB]
D104  1SMB5952BT3G  value 130V  [SMB]
D105  SZMM3Z18VST1G  value 18V  [SOD-323]
D106  SZMM3Z18VST1G  value 18V  [SOD-323]
D107  SZMM3Z18VST1G  value 18V  [SOD-323]
D108  STTH1R06A  [SMA]
D109  DDZ26Q-7  value 26V  [SOD-123]
D110  ES1JAF  Vr_V: 600V  [SMAF]
D111  ES1JAF  Vr_V: 600V  [SMAF]
D112  STTH112A  [SMA]
D113  XBS104S13R-G  [SOD-323]
D114  MM3Z12VST1G  value 12V  [SOD-323]
D115  MM3Z15VST1G  value 15V  [SOD-323]
OVP_OTP  5012  [Keystone5012]  (value not drawn)
Q101  2N7002Q-7-F  [SOT-23]
Q102  BSS126H6327XTSA2  [SOT-23]
Q103  BSS126H6327XTSA2  [SOT-23]
Q104  FZT651TA  [SOT-223]
Q105  2N7002W-7-F  [SOT-323]
R101  ValueDisplayed: 3.24M  [1206]  (hidden comment: CRCW12063M24FKEA)
R102  ValueDisplayed: 1.50M  [0603]  (hidden comment: RC0603FR-071M5L)
R103  ValueDisplayed: 1.0k  [0603]  (hidden comment: CRCW06031K00JNEA)
R104  ValueDisplayed: 1.00M  [0603]  (hidden comment: RC0603FR-071ML)
R105  ValueDisplayed: 1.00M  [0603]  (hidden comment: RC0603FR-071ML)
R106  ValueDisplayed: 220  [0603]  (hidden comment: RC0603FR-07220RL)
R107  ValueDisplayed: 10k  [0603]  (hidden comment: CRCW060310K0JNEA)
R108  ValueDisplayed: 0  [0603]  (hidden comment: ERJ-3GEY0R00V)
R109  ValueDisplayed: 0  [0603]  (hidden comment: ERJ-3GEY0R00V)
R110  ValueDisplayed: 2.20  [0603]  (hidden comment: ERJ-3RQF2R2V)
R111  ValueDisplayed: 2.43M  [1206]  (hidden comment: CRCW12062M43FKEA)
R112  ValueDisplayed: 2.43M  [1206]  (hidden comment: CRCW12062M43FKEA)
R113  ValueDisplayed: 2.43M  [1206]  (hidden comment: CRCW12062M43FKEA)
R114  Res_ohm: 36k  [0603]  (hidden comment: CRCW060336K0JNEA)
R115  ValueDisplayed: 590k  [0603]  (hidden comment: RC0603FR-07590KL)
R116  ValueDisplayed: 71.5k  [0603]  (hidden comment: RC0603FR-0771K5L)
R117  ValueDisplayed: 604k  [0603]  (hidden comment: RC0603FR-07604KL)
R118  ValueDisplayed: 165k  [0603]  (hidden comment: RC0603FR-07165KL)
R119  ValueDisplayed: 15.0k  [0603]  (hidden comment: RG1608P-153-B-T5)
R120  ValueDisplayed: 15.0k  [0603]  (hidden comment: RG1608P-153-B-T5)
R121  B57371V2474J060  [FP-B57371V2474J060_0603-MFG]
R122  ValueDisplayed: 2.20  [0603]  (hidden comment: ERJ-3RQF2R2V)
R123  ValueDisplayed: 2.43M  [1206]  (hidden comment: CRCW12062M43FKEA)
R124  ValueDisplayed: 2.43M  [1206]  (hidden comment: CRCW12062M43FKEA)
R125  ValueDisplayed: 3.24M  [1206]  (hidden comment: CRCW12063M24FKEA)
R126  ValueDisplayed: 715k  [0603]  (hidden comment: RC0603FR-07715KL)
R127  ValueDisplayed: 3.24M  [1206]  (hidden comment: CRCW12063M24FKEA)
R128  ValueDisplayed: 0  [1206]  (hidden comment: ERJ-8GEY0R00V)
R129  ValueDisplayed: 200k  [0603]  (hidden comment: RC0603FR-07200KL)
U101  UCC256602DDBR  [DDB0014A-MFG]
U102  PartNumber: UCC5350SBDR  [D0008A-MFG]  (hidden comment: UCC5350MCQDRQ1)

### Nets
PGND: C102.2 C103.2 C104.2 C105.2 C106.2 C108.2 C109.2 C110.2 C113.2 C115.2(-) C116.2 D104.2(A) D105.2(A) D107.2(A) D111.2(A) D115.2(A) Q101.2(S) R102.1 R109.2 R114.1 R116.1 R118.1 R119.1 R121.1 U101.10(GNDP)
5VP: 5VP.1 C108.1 D113.1(K) R115.2 R117.2 R126.2 U101.8(5VP) ; off-sheet 5VP
BLK: BLK.1 C105.1 R113.1 R114.2 U101.3(BLK) ; off-sheet BLK
FB: U101.5(FB) ; off-sheet FB
HB: C107.1 C111.1 D108.1(K) U101.14(HB) U102.1(VCC1) ; off-sheet HB
HO: U102.6(OUTH) ; off-sheet HO
HO_CTRL: U101.15(HO) U102.2(IN+) ; off-sheet HO_CTRL
HO_OFF: U102.7(OUTL) ; off-sheet HO_OFF
HS: C112.1 C114.1 D110.1(K) U102.8(VEE2) ; off-sheet HS
HS_CTRL: C107.2 C111.2 C112.2 C113.1 D110.2(A) D111.1(K) U101.16(HS) U102.3(IN-) U102.4(GND1) ; off-sheet HS_CTRL
ISNS: U101.9(ISNS) ; off-sheet ISNS
LL: C109.1 R117.1 R118.2 U101.6(LL) ; off-sheet LL
LO: U101.11(LO) ; off-sheet LO
OVP/OTP: C110.1 D109.2(A) OVP_OTP.1 R119.2 R121.2 U101.4(OVP/OTP) ; off-sheet OVP/OTP
TSET: C106.1 R115.1 R116.2 U101.7(TSET) ; off-sheet TSET
VB: Q104.2(C) Q104.4(C) R107.1 R108.1 R120.2 ; off-sheet VB
VCC: C103.1 C104.1 C115.1(+) D106.1(K) Q104.3(E) Q105.3(D) R106.1 R108.2 R122.1 R129.2 U101.12(VCCP) ; off-sheet VCC
VIN: C101.2 Q102.3(D) R123.2 R127.2 ; off-sheet VIN
NetC101_1: C101.1 D101.1(K) D114.2(A) Q102.1(G) R101.1 R104.1
NetC102_1: C102.1 D113.2(A) Q101.1(G) R102.2 R126.1
NetC114_2: C114.2 D112.1(K) U102.5(VCC2)
NetC116_1: C116.1 Q105.2(S) R110.1
NetD101_2: D101.2(A) D102.1(K)
NetD102_2: D102.2(A) D103.1(K)
NetD103_2: D103.2(A) D104.1(K)
NetD105_1: D105.1(K) D106.2(A) Q103.1(G) R103.2 R105.1
NetD107_1: D107.1(K) Q104.1(B) R107.2
NetD108_2: D108.2(A) R110.2
NetD109_1: D109.1(K) R120.1
NetD112_2: D112.2(A) R122.2
NetD114_1: D114.1(K) Q102.2(S) Q103.3(D) R104.2 R128.1
NetD115_1: D115.1(K) Q105.1(G) R129.1
NetQ101_3: Q101.3(D) R103.1
NetQ103_2: Q103.2(S) R105.2 R106.2
NetR101_2: R101.2 R125.1
NetR109_1: R109.1 R128.2 U101.1(HV)
NetR111_1: R111.1 R112.2
NetR111_2: R111.2 R124.1
NetR112_1: R112.1 R113.2
NetR123_1: R123.1 R124.2
NetR125_2: R125.2 R127.1

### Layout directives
net class HV: HO, HO_OFF, HS, NetC114_2, VIN
net class MV: HB, HO_CTRL, HS_CTRL, NetC101_1, NetD101_2, NetD102_2, NetD103_2, NetD114_1, NetR101_2, NetR111_1, NetR111_2, NetR112_1, NetR123_1, NetR125_2

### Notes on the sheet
- Startup Circuit

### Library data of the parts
5VP = CMP-0055147-2: as VAUX on sheet PMP41133_RevC_Power Stage
BLK OVP_OTP = CMP-0055149-2: as HG on sheet PMP41133_RevC_Power Stage
C101 = CMP-0009029-1: CAP, CERM, 10 pF, 1000 V, +/- 5%, C0G/NP0, 1206; Manufacturer: Vishay-Vitramon; TaMin_C: -55°C; Polarized: N; SizeAreaWB_mm2: 10.92; Value1: Unknown; U/M: EA; Value: 10pF; TaMax_C: 125°C; SizeZ_mm: 1.35; SizeX_mm: 3.2; SizeY_mm: 1.6; Value2: 1000V; SizeArea_mm2: 5.12; AEC Category: Q200
C102 = CMP-0007355-2: CAP, CERM, 10 uF, 35 V, +/- 20%, X5R, 0603; Manufacturer: Nichicon; TaMin_C: -55°C; Polarized: N; SizeAreaWB_mm2: 4.68; Value1: Unknown; U/M: EA; Value: 10uF; TaMax_C: 85°C; SizeZ_mm: 1; SizeX_mm: 1.6; SizeY_mm: 0.8; SizeArea_mm2: 1.28; Cap_F: 10µF; AEC Category: Q200
C103 C104 C116 = CMP-0076705-3: CAP, CERM, 1 µF, 25 V,+/- 10%, X7R, AEC-Q200 Grade 1, 0603; Manufacturer: TDK; SizeAreaWB_mm2: 4.68; SizeArea_mm2: 1.28; AEC Qualified: Y; AEC Category: Q200; Value: 1uF; TaMax_C: 125°C; SizeZ_mm: 1.0; AEC Grade: 1; Polarized: N; TaMin_C: -55°C; SizeY_mm: 0.8; U/M: EA; SizeX_mm: 1.6; Cap_Case: 1.6x0.8x0.8mm
C105 = CMP-0007433-1: as C15 on sheet PMP41133_RevC_Power Stage
C106 = CMP-0006982-4: CAP, CERM, 220 pF, 50 V, +/- 10%, X7R, 0603; Manufacturer: Kemet; TaMin_C: -55°C; Polarized: N; SizeAreaWB_mm2: 4.68; Value1: Unknown; U/M: EA; Value: 220pF; TaMax_C: 125°C; SizeZ_mm: 1; SizeX_mm: 1.6; SizeY_mm: 0.8; Value2: 50V; SizeArea_mm2: 1.28; AEC Category: Q200
C107 C114 = CMP-0006861-2: CAP, CERM, 0.1 uF, 50 V, +/- 10%, X7R, 0603; Manufacturer: Kemet; TaMin_C: -55°C; Polarized: N; SizeAreaWB_mm2: 4.68; Value1: Unknown; U/M: EA; Value: 0.1uF; TaMax_C: 125°C; SizeZ_mm: 1; SizeX_mm: 1.6; SizeY_mm: 0.8; SizeArea_mm2: 1.28; AEC Category: Q200
C108 = CMP-0008346-1: CAP, CERM, 4.7 uF, 25 V, +/- 10%, X7R, 0805; Manufacturer: MuRata; TaMin_C: -55°C; Polarized: N; SizeAreaWB_mm2: 6.75; Value1: Unknown; U/M: EA; Value: 4.7uF; TaMax_C: 125°C; SizeZ_mm: 1.45; SizeX_mm: 2; SizeY_mm: 1.25; Cap_Case: 0805; SizeArea_mm2: 2.5; AEC Category: Q200
C109 = CMP-0006976-5: CAP, CERM, 1000 pF, 50 V, +/- 10%, X7R, 0603; Manufacturer: Kemet; TaMin_C: -55°C; Polarized: N; SizeAreaWB_mm2: 4.68; Value1: Unknown; U/M: EA; Value: 1000pF; TaMax_C: 125°C; SizeZ_mm: 1; SizeX_mm: 1.6; SizeY_mm: 0.8; Value2: 50V; SizeArea_mm2: 1.28; AEC Category: Q200
C110 = CMP-0006983-4: CAP, CERM, 2200 pF, 50 V, +/- 10%, X7R, 0603; Manufacturer: Kemet; TaMin_C: -55°C; Polarized: N; SizeAreaWB_mm2: 4.68; Value1: Unknown; U/M: EA; Value: 2200pF; TaMax_C: 125°C; SizeZ_mm: 1; SizeX_mm: 1.6; SizeY_mm: 0.8; Value2: 50V; SizeArea_mm2: 1.28; AEC Category: Q200
C111 = CMP-0084679-1: CAP, CERM, 0.1 µF, 25 V,+/- 10%, X7R, AEC-Q200 Grade 1, 0603; Manufacturer: MuRata; TaMin_C: -55°C; Polarized: N; SizeAreaWB_mm2: 4.68; U/M: EA; Value: 0.1uF; TaMax_C: 125°C; SizeZ_mm: 1; SizeX_mm: 1.6; SizeY_mm: 0.8; Value2: 25V; SizeArea_mm2: 1.28; AEC Qualified: Y; AEC Category: Q200; ValueDisplayed: 0.1µF
C112 C113 = CMP-0008902-1: CAP, CERM, 68 pF, 1000 V, +/- 5%, U2J, 1206; Manufacturer: MuRata; TaMin_C: -55°C; Polarized: N; SizeAreaWB_mm2: 10.92; Value1: Unknown; U/M: EA; Value: 68pF; TaMax_C: 125°C; SizeZ_mm: 1.35; SizeX_mm: 3.2; SizeY_mm: 1.6; Value2: 1000V; SizeArea_mm2: 5.12; AEC Category: Q200
C115 = CMP-0010327-2: as C11 on sheet PMP41133_RevC_Power Stage
D101-D104 = CMP-0005620-4: Diode, Zener, 130 V, 550 mW, SMB; Manufacturer: ON Semiconductor; SizeX_mm: 5.6; SizeY_mm: 3.81; AEC Category: Q101; Value1: 0.55W; SizeAreaWB_mm2: 44.156; SizeZ_mm: 2.6; Power_W: 550mW; RJA_CperW: 226; SizeArea_mm2: 21.336
D105-D107 = CMP-0085765-1: as D5 on sheet PMP41133_RevC_Power Stage
D108 = CMP-0076908-2: Diode, Ultrafast, 600 V, 1 A, SMA; Manufacturer: STMicroelectronics; Green_REACh: Passed; SizeAreaWB_mm2: 37.3428; Vf_V: 1V; Value: 600V; Io_A: 1A; Green_Lifecycle: Active; SizeZ_mm: 2.87; RJC_CperW: 30.0; SizeArea_mm2: 16.3228; TJmax_C: 175°C; SizeY_mm: 2.92; AEC Category: Q101; SizeX_mm: 5.59
D109 = CMP-0085157-1: Diode, Zener, 26 V, 500 mW, AEC-Q101, SOD-123; Manufacturer: Diodes Inc.; Power_W: 500mW; SizeArea_mm2: 6.545; AEC Category: Q101; SizeAreaWB_mm2: 13.095; Value1: 0.5W; SizeZ_mm: 1.35; AEC Qualified: Y; SizeY_mm: 1.7; RJA_CperW: 425; SizeX_mm: 3.85
D110 D111 = CMP-0029162-2: Diode, Ultrafast, 600 V, 1 A, AEC-Q101, SMAF; Manufacturer: Fairchild Semiconductor; Io_A: 1A; Green_Lifecycle: Not Set; SizeAreaWB_mm2: 19.95; Green_REACh: Incomplete; TJmax_C: 150°C; Value: 600V; SizeZ_mm: 1; SizeX_mm: 4.7; SizeY_mm: 2.5; Vf_V: 1.7V; SizeArea_mm2: 11.75; AEC Qualified: Y; AEC Category: Q101
D112 = CMP-0077081-1: Diode, Ultrafast, 1200 V, 1 A, SMA; Manufacturer: STMicroelectronics; SizeAreaWB_mm2: 37.3428; Vr_V: 1.2kV; SizeArea_mm2: 16.3228; AEC Qualified: N; TJmax_C: 175°C; AEC Category: Q101; Value: 1200V; SizeZ_mm: 2.87; Green_REACh: Incomplete; Io_A: 1A; Vf_V: 1.9V; SizeY_mm: 2.92; Green_Lifecycle: Not Set; U/M: EA; SizeX_mm: 5.59
D113 = CMP-0028802-1: Diode, Schottky, 40 V, 1 A, SOD-323; Manufacturer: Torex USA Corporation; Io_A: 1A; Green_Lifecycle: Not Set; SizeAreaWB_mm2: 8.695; Vr_V: 40V; Green_REACh: Incomplete; TJmax_C: 125°C; U/M: EA; Value: 40V; SizeZ_mm: 1; SizeX_mm: 2.7; SizeY_mm: 1.35; Vf_V: 540mV; Value2: 0.54V; SizeArea_mm2: 3.645; AEC Qualified: N; AEC Category: Q101
D114 = CMP-0085757-1: Diode, Zener, 12 V, 300 mW, SOD-323; Manufacturer: ON Semiconductor; SizeAreaWB_mm2: 8.695; AEC Qualified: N; SizeZ_mm: 1; Power_W: 300mW; AEC Category: Q101; SizeArea_mm2: 3.645; Value1: 0.3W; SizeX_mm: 2.7; RJA_CperW: 416; SizeY_mm: 1.35
D115 = CMP-0085762-1: Diode, Zener, 15 V, 300 mW, SOD-323; Manufacturer: ON Semiconductor; Value1: 0.3W; Power_W: 300mW; AEC Category: Q101; SizeX_mm: 2.7; SizeArea_mm2: 3.645; SizeAreaWB_mm2: 8.695; SizeY_mm: 1.35; AEC Qualified: N; RJA_CperW: 416; SizeZ_mm: 1
Q101 = CMP-0085603-1: MOSFET, N-CH, 60 V, 0.115 A, AEC-Q101, SOT-23; Manufacturer: Diodes Inc.; Alternate Manufacturer: None; SizeAreaWB_mm2: 14; Value: 60V; QgTyp_nC: 0.223; IdsMax_A: 115mA; AEC Category: Q101; SizeY_mm: 3; SizeArea_mm2: 7.5; SizeX_mm: 2.5; SizeZ_mm: 1.1; Value1: ? ohm; ChMode: Enhancement; Vgs_V: 20V; ChType: N; AEC Qualified: Y; Value2: 0.223 nC
Q102 Q103 = CMP-0067574-1: MOSFET, N-CH, 600 V, 0.021 A, AEC-Q101, SOT-23; Alternate Manufacturer: None; Manufacturer: Infineon Technologies; QgTyp_nC: 1.4; SizeAreaWB_mm2: 14.0; Vgs_V: 20V; Value1: ? ohm; VdsMax_V: 600V; U/M: EA; Value: 600V; IdsMax_A: 21mA; SizeZ_mm: 1.1; SizeX_mm: 2.5; SizeY_mm: 3.0; Value2: 1.4 nC; SizeArea_mm2: 7.5; ChType: N; AEC Qualified: Y; AEC Category: Q101
Q104 = CMP-0000393-1: Transistor, NPN, 60 V, 3 A, SOT-223; Manufacturer: Zetex; TaMax_C: 150°C; Value2: 300; Value1: 3 A; Vcesat1_V: 430mV; SizeX_mm: 6.5; SizeY_mm: 7; TaMin_C: -55°C; IcRated_A: 3A; CompType: BJT; SizeZ_mm: 1.6; Value: 60 V; SizeArea_mm2: 45.5; NPN: 1; Vceo_V: 60V; PNP: 0; AEC Category: Q101; SizeAreaWB_mm2: 76.5; U/M: EA
Q105 = CMP-0000776-1: MOSFET, N-CH, 60 V, 0.115 A, SOT-323; Alternate Manufacturer: None; Manufacturer: Diodes Inc.; SizeZ_mm: 1.1; ChType: N; Value1: 7; VdsMax_V: 60V; SizeX_mm: 2.2; Vgs_V: 20V; Value: 60V; Rdson45_ohm: 7.5; SizeArea_mm2: 4.84; AEC Category: Q101; IdsMax_A: 115mA; SizeAreaWB_mm2: 10.24; U/M: EA
R101 R125 R127 = CMP-0016959-3: RES, 3.24 M, 1%, 0.25 W, AEC-Q200 Grade 0, 1206; Manufacturer: Vishay-Dale; Power_W: 250mW; TempCo: 100 ppm/C; Value_Code: 3M24; Value: 3.24Meg; EIA_Code: E96; SizeX_mm: 3.2; SizeY_mm: 1.6; SizeZ_mm: 1.35; Value2: 0.25W; SizeArea_mm2: 5.12; AEC Qualified: Y; VDC_V: 200V; AEC Category: Q200; AEC Grade: 0
R102 = CMP-0022898-4: RES, 1.50 M, 1%, 0.1 W, 0603; Manufacturer: Yageo; Power_W: 100mW; TempCo: 100 ppm/C; Value_Code: 1M50; Value: 1.50Meg; EIA_Code: E96; Res_ohm: 1.5M; SizeX_mm: 1.6; SizeY_mm: 0.8; SizeZ_mm: 1; Value2: 0.1W; SizeArea_mm2: 1.28; AEC Qualified: N; VDC_V: 75V; AEC Category: Q200; SizeAreaWB_mm2: 4.68
R103 = CMP-0025729-1: RES, 1.0 k, 5%, 0.1 W, 0603; Manufacturer: Vishay-Dale; Power_W: 100mW; TempCo: 200 ppm/C; Value_Code: 1k00; U/M: EA; Value: 1.0k; EIA_Code: E24; Res_ohm: 1k; SizeX_mm: 1.6; SizeY_mm: 0.8; SizeZ_mm: 1; Value2: 0.1W; SizeArea_mm2: 1.28; VDC_V: 75V; AEC Category: Q200
R104 R105 = CMP-0022899-4: RES, 1.00 M, 1%, 0.1 W, 0603; Manufacturer: Yageo; Power_W: 100mW; TempCo: 100 ppm/C; Value_Code: 1M00; Value: 1.00Meg; EIA_Code: E96; Res_ohm: 1M; SizeX_mm: 1.6; SizeY_mm: 0.8; SizeZ_mm: 1; Value2: 0.1W; SizeArea_mm2: 1.28; AEC Qualified: N; VDC_V: 75V; AEC Category: Q200; SizeAreaWB_mm2: 4.68
R106 = CMP-0022918-5: RES, 220, 1%, 0.1 W, 0603; Manufacturer: Yageo; Power_W: 100mW; TempCo: 100 ppm/C; Value_Code: 220R; Value: 220; SizeX_mm: 1.6; SizeY_mm: 0.8; SizeZ_mm: 1; Value2: 0.1W; SizeArea_mm2: 1.28; AEC Qualified: N; VDC_V: 75V; AEC Category: Q200; SizeAreaWB_mm2: 4.68
R107 = CMP-0025701-2: RES, 10 k, 5%, 0.1 W, 0603; Manufacturer: Vishay-Dale; Power_W: 100mW; TempCo: 200 ppm/C; Value_Code: 10k0; U/M: EA; Value: 10k; EIA_Code: E24; SizeX_mm: 1.6; SizeY_mm: 0.8; SizeZ_mm: 1; Value2: 0.1W; SizeArea_mm2: 1.28; VDC_V: 75V; AEC Category: Q200
R108 R109 = CMP-0025874-2: RES, 0, 5%, 0.1 W, 0603; Manufacturer: Panasonic; Power_W: 100mW; TempCo: 600 ppm/C; Value_Code: 0000; U/M: EA; Value: 0; EIA_Code: E24; SizeX_mm: 1.6; SizeY_mm: 0.8; SizeZ_mm: 1; Value2: 0.1W; SizeArea_mm2: 1.28; VDC_V: 50V; AEC Category: Q200
R110 R122 = CMP-0022711-2: RES, 2.20, 1%, 0.1 W, 0603; Manufacturer: Panasonic; Power_W: 100mW; TempCo: 200 ppm/C; Value_Code: 2R20; U/M: EA; Value: 2.20; Res_ohm: 2.2; SizeX_mm: 1.6; SizeY_mm: 0.8; SizeZ_mm: 1; Value2: 0.1W; SizeArea_mm2: 1.28; CompType: Resistor; AEC Category: Q200
R111-R113 R123 R124 = CMP-0016869-1: RES, 2.43 M, 1%, 0.25 W, 1206; Manufacturer: Vishay-Dale; Power_W: 250mW; TempCo: 100 ppm/C; Value_Code: 2M43; U/M: EA; Value: 2.43Meg; EIA_Code: E96; SizeX_mm: 3.2; SizeY_mm: 1.6; SizeZ_mm: 1.35; Value2: 0.25W; SizeArea_mm2: 5.12; VDC_V: 200V; AEC Category: Q200
R114 = CMP-0025790-4: RES, 36 k, 5%, 0.1 W, AEC-Q200 Grade 0, 0603; Manufacturer: Vishay-Dale; AEC Qualified: Y; SizeX_mm: 1.6; Value: 36k; Power_W: 100mW; SizeArea_mm2: 1.28; SizeZ_mm: 1; Value2: 0.1W; SizeY_mm: 0.8; AEC Grade: 0; TempCo: 200 ppm/C; VDC_V: 75V; EIA_Code: E24; Value_Code: 36k0; AEC Category: Q200
R115 = CMP-0023193-4: RES, 590 k, 1%, 0.1 W, 0603; Manufacturer: Yageo; Power_W: 100mW; TempCo: 100 ppm/C; Value: 590k; EIA_Code: E96; SizeX_mm: 1.6; SizeY_mm: 0.8; SizeZ_mm: 1; Value2: 0.1W; SizeArea_mm2: 1.28; AEC Qualified: N; VDC_V: 75V; AEC Category: Q200; SizeAreaWB_mm2: 4.68
R116 = CMP-0023259-5: RES, 71.5 k, 1%, 0.1 W, 0603; Manufacturer: Yageo; Power_W: 100mW; TempCo: 100 ppm/C; Value_Code: 71k5; Value: 71.5k; EIA_Code: E96; SizeX_mm: 1.6; SizeY_mm: 0.8; SizeZ_mm: 1; Value2: 0.1W; SizeArea_mm2: 1.28; AEC Qualified: N; VDC_V: 75V; AEC Category: Q200; SizeAreaWB_mm2: 4.68
R117 = CMP-0023210-4: RES, 604 k, 1%, 0.1 W, 0603; Manufacturer: Yageo; Power_W: 100mW; TempCo: 100 ppm/C; Value: 604k; EIA_Code: E96; SizeX_mm: 1.6; SizeY_mm: 0.8; SizeZ_mm: 1; Value2: 0.1W; SizeArea_mm2: 1.28; AEC Qualified: N; VDC_V: 75V; AEC Category: Q200; SizeAreaWB_mm2: 4.68
R118 = CMP-0022824-4: RES, 165 k, 1%, 0.1 W, 0603; Manufacturer: Yageo; Power_W: 100mW; TempCo: 100 ppm/C; Value: 165k; EIA_Code: E96; SizeX_mm: 1.6; SizeY_mm: 0.8; SizeZ_mm: 1; Value2: 0.1W; SizeArea_mm2: 1.28; AEC Qualified: N; VDC_V: 75V; AEC Category: Q200; SizeAreaWB_mm2: 4.68
R119 R120 = CMP-0023441-3: RES, 15.0 k, 0.1%, 0.1 W, 0603; Manufacturer: Susumu Co Ltd; Power_W: 100mW; TempCo: 25 ppm/C; Value_Code: 15k0; U/M: EA; Value: 15.0k; EIA_Code: E192; Res_ohm: 15k; SizeX_mm: 1.6; SizeY_mm: 0.8; SizeZ_mm: 1; Value2: 0.1W; SizeArea_mm2: 1.28; VDC_V: 75V; AEC Category: Q200
R121 = CMP-0096703-1: NTC Thermistor 470k 0603 (1608 Metric); Manufacturer: TDK; AEC Qualified: No; Res_ohm: 470kΩ; Power_W: 180mW; B 25 50: 4386K; B 25 100: 4480K; SizeZ_mm: 0.9mm; B 25 85: 4455K; B Tolerance: 3%; Tolerance_%: 5%
R126 = CMP-0023257-4: RES, 715 k, 1%, 0.1 W, 0603; Manufacturer: Yageo; Power_W: 100mW; TempCo: 100 ppm/C; Value: 715k; EIA_Code: E96; SizeX_mm: 1.6; SizeY_mm: 0.8; SizeZ_mm: 1; Value2: 0.1W; SizeArea_mm2: 1.28; AEC Qualified: N; VDC_V: 75V; AEC Category: Q200; SizeAreaWB_mm2: 4.68
R128 = CMP-0018748-3: RES, 0, 5%, 0.25 W, AEC-Q200 Grade 0, 1206; Manufacturer: Panasonic; Power_W: 250mW; TempCo: 600 ppm/C; Value_Code: 0000; Value: 0; EIA_Code: E24; SizeX_mm: 3.2; SizeY_mm: 1.6; SizeZ_mm: 1.35; Value2: 0.25W; SizeArea_mm2: 5.12; AEC Qualified: Y; VDC_V: 200V; AEC Category: Q200; SizeAreaWB_mm2: 10.92
R129 = CMP-0022901-4: RES, 200 k, 1%, 0.1 W, 0603; Manufacturer: Yageo; Power_W: 100mW; TempCo: 100 ppm/C; Value: 200k; EIA_Code: E96; SizeX_mm: 1.6; SizeY_mm: 0.8; SizeZ_mm: 1; Value2: 0.1W; AEC Qualified: N; VDC_V: 75V; AEC Category: Q200; SizeArea_mm2: 1.28; SizeAreaWB_mm2: 4.68
U101 = CMP-0095298-2: 750kHz Wide VIN/VOUT Range LLC Controller Optimized for Light Load Efficiency; Manufacturer: Texas Instruments; TJmax_C: +150°C; AEC Qualified: No; TaMin_C: -40°C; TaMax_C: +125°C; Standoff Height: 0.1mm; Number Of Outputs: 2; Output Type: Other; Switching Frequency: 30-750kHz; Max Supply Voltage: 18.5V; SizeZ_mm: 1.75mm; AEC Category: Q200; CompType: IC
U102 = CMP-0122620-1: 3kVrms, 5A/5A single-channel isolated gate driver with miller clamp or split out & 8V or 12V UVLO; Manufacturer: Texas Instruments; Number Of Outputs: 2; Rise Time: 10ns; Standoff Height: 0.11mm; SizeZ_mm: 1.75mm; TJmax_C: +150°C; Min Supply Voltage: 3V; Propagation Delay: 65ns; Max Supply Voltage: 33V; AEC Qualified: No; Max Power Dissipation: 1.14W; TaMax_C: +125°C; TaMin_C: -40°C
